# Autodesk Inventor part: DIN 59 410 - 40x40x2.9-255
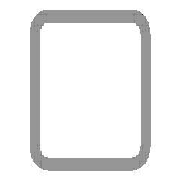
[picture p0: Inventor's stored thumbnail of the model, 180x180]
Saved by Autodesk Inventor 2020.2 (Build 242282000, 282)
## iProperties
Manager: www.cadconsulting.pl
Company: Fabian Stasiak CAD Consulting
_CCFamilyMember: 10
_CCFamilyDisplayName: DIN 59410 (Kwadrat) - Rurki stalowe o przekroju kwadratowym formowane na gorąco
_FrameMemberDoc: Frame Member File
_Version: 15.0.0
_GetPNFromCC: 1
Created: 2015-01
Part Number: DIN 59 410 - 40x40x2.9-255
Material: Stal, miękka
Description: Rurki stalowe o przekroju kwadratowym formowane na gorąco
Document SubType Name: Modellieren
Standard: DIN
Designer: F.Stasiak
Standards Organization: DIN
Language: pl-PL
Size Designation: 40x40x2.9
Categories: <MemberInstance><Categories><Category DisplayName="Kształtowniki konstrukcyjne" InternalName="089c4875-fa83-4c05-b084-43b9cc11f5ed" Mnemonic="GRDR"><CategoryPar
Stock Number: 40x40x2.9
Density: 7.85 g/cm^3
Appearance: Częściowo polerowana
Mass: 818.12 g
Surface Area: 726.927 cm^2
Volume: 104.219 cm^3
Catalog Web Link: www.expertbooks.pl
IsCustomPart: 1
G_L: 255,000 mm
G_W: 40,000 mm
G_H: 40,000 mm
+3517EC73-A6E2-4A4B-8A75-0E1C8A6AE732+CUTDETAIL1: Wytnij
Author: F.Stasiak
Subject: Zbiór ćwiczeń. Autodesk Inventor 2020. Kurs Professional
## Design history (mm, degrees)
node "Płaszczyzna początkowa"
node "Płaszczyzna końcowa"
sketch "Szkic"
  geometry: L1 (-14.2, 20)-(14.2, 20); L2 (20, 14.2)-(20, -14.2); L3 (14.2, -20)-(-14.2, -20); L4 (-20, -14.2)-(-20, 14.2); L5 (-29.682, 0)-(29.682, 0) reference; L6 (0, -29.682)-(0, 29.682) reference; L7 (-14.2, 17.1)-(14.2, 17.1); L8 (17.1, 14.2)-(17.1, -14.2); L9 (14.2, -17.1)-(-14.2, -17.1); L10 (-17.1, -14.2)-(-17.1, 14.2); A1 r 5.8 centre (-14.2, 14.2) between (-14.2, 20) and (-20, 14.2); A2 r 5.8 centre (14.2, 14.2) between (20, 14.2) and (14.2, 20); A3 r 5.8 centre (14.2, -14.2) between (14.2, -20) and (20, -14.2); A4 r 5.8 centre (-14.2, -14.2) between (-20, -14.2) and (-14.2, -20); A5 r 2.9 centre (-14.2, 14.2) between (-14.2, 17.1) and (-17.1, 14.2); A6 r 2.9 centre (14.2, 14.2) between (17.1, 14.2) and (14.2, 17.1); A7 r 2.9 centre (14.2, -14.2) between (14.2, -17.1) and (17.1, -14.2); A8 r 2.9 centre (-14.2, -14.2) between (-17.1, -14.2) and (-14.2, -17.1); 3 further points
  constraints: 16 end point, 16 point on circle, 8 centre point, 8 tangent, 6 point on line, 4 parallel, 3 equal radius, 3 perpendicular, 1 horizontal, 7 other
  dimensions: "b" = 40 distance of point (-20, 20) point (20, 20); "msp_r" = 5.8 radius of A1 (= 2 x ParT); "d8" = 20 distance between parallel lines of L4 L6 (= d9); "d9" = 20 distance between parallel lines of L3 L5 (= 0.5 x b); "d10" = 2.9 distance between parallel lines of L3 L9 (= ParT)
extrude "Bryła" new body sketch "Szkic" taper "d4" = 0 deg; stored distance "NLG" = 10
node "Driven Length"
  sketch "Sketch2"
    geometry: L1 (0, 0)-(10, 0) reference
    constraints: 2 end point, 1 horizontal
  workplane "Work Plane3"
  sketch "Sketch3"
    geometry: L1 (-2, 20)-(12, 20) reference; L2 (-2, 275)-(12, 275) reference
    dimensions: "d14" = 255 distance between parallel lines of L1 L2 (derived)
node "Płaszczyzna konstrukcyjna4"
feature "Podział1"
node "Płaszczyzna konstrukcyjna5"
feature "Podział2"
body "Solid1"
other parameters: "ParT" = 2.9, "G_OFFSET_END" = -25 [user parameter; used in 1 equation term], "d12" = 275 (= G_OFFSET_END + B_L), "G_L" = 255 (= d14) [user parameter], "d13" = 90 deg
